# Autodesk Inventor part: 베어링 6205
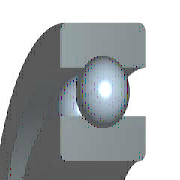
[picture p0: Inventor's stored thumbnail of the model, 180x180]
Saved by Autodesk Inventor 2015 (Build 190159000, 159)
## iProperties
Created: 2015-10
Part Number: 베어링 6205
Material: 강, 연강
Description: 깊은 그루브 볼 베어링
Document SubType Name: Modeling
Standard: KS B 2023
Designer: mdu
Standards Organization: KS
Language: ko-KR
Size Designation: 6205 - 25 x 52 x 15
Categories: <MemberInstance><Categories><Category DisplayName="샤프트 부품" InternalName="7f7aeb1f-a693-4053-b835-cee3144e0d98" Mnemonic="SHFT"><Category DisplayName="베어링" Inter
Density: 7.86 g/cm^3
Appearance: 노란색
Mass: 129.543 g
Surface Area: 107.326 cm^2
Volume: 16.4813 cm^3
IsCustomPart: 1
Author: mdu
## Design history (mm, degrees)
sketch "스케치" dims "d0" = 7.02 (= -0.26 x WD + 0.26 x BD)
  geometry: L1 (3.99, 19.25)-(11.01, 19.25); L2 (7.5, 19.25)-(7.5, 15.74); L3 (7.5, 19.25)-(7.5, 22.76); L4 (4.892, 16.901)-(0, 16.901); L5 (0, 12.5)-(15, 12.5); L6 (4.892, 21.599)-(0, 21.599); L7 (0, 26)-(15, 26); L8 (15, 12.5)-(15, 16.901); L9 (10.108, 16.901)-(15, 16.901); L10 (10.108, 21.599)-(15, 21.599); L11 (15, 26)-(15, 21.599); L12 (-1.4, 0)-(8.4, 0) reference; L13 (0, -0.3)-(0, 5.3) reference
  constraints: 22 end point, 4 point on line, 2 collinear, 2 perpendicular, 2 symmetric about line, 1 midpoint, 1 parallel, 14 other
  dimensions: "d9" = 25 diameter of L5 L12 (= WD); "d11" = 52 diameter of L7 L12 (= BD); "d12" = 15 distance between parallel lines of L8 L13 (= KB); "d13" = 33.802 diameter of L9 L12 (= 0.326 x BD + 0.674 x WD)
revolve "본체" stored, may be unused: angle "d6" = 90 deg
revolve "볼" stored, may be unused: angle "d7" = 90 deg
pattern_circular "IDS_ARRAYBALL[SIMPL:T]" dims angle "d3" = 360 deg
body "Solid1"
fillet "모깎기1" dims "d1" = 1 (= KRS)
other parameters: "WD" = 25 [user parameter; used in 5 equation terms], "BD" = 52 [user parameter; used in 5 equation terms], "KB" = 15 [user parameter; used in 1 equation term], "KRS" = 1 [user parameter; used in 1 equation term], "d4" = 0, "d5" = 0, "d8" = 0, "d14" = 0, "d15" = 0, "BBA" = 0 [user parameter], "BC0" = 7800000 [user parameter], "BC" = 1.4e+07 [user parameter], "BR" = 26 (= 0.5 x BD) [user parameter], "WR" = 12.5 (= 0.5 x WD) [user parameter]
